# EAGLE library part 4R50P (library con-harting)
CONNECTOR
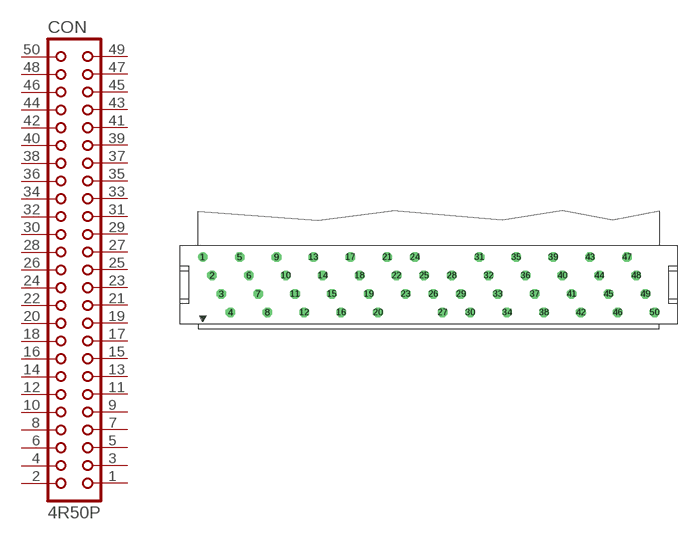
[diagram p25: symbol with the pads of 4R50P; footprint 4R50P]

Designator prefix CON

## 4R50P (OC_FARNELL: unknown; OC_NEWARK: unknown)  [4R50P]
1  1  pas
2  2  pas
3  3  pas
4  4  pas
5  5  pas
6  6  pas
7  7  pas
8  8  pas
9  9  pas
10  10  pas
11  11  pas
12  12  pas
13  13  pas
14  14  pas
15  15  pas
16  16  pas
17  17  pas
18  18  pas
19  19  pas
20  20  pas
21  21  pas
22  22  pas
23  23  pas
24  24  pas
25  25  pas
26  26  pas
27  27  pas
28  28  pas
29  29  pas
30  30  pas
31  31  pas
32  32  pas
33  33  pas
34  34  pas
35  35  pas
36  36  pas
37  37  pas
38  38  pas
39  39  pas
40  40  pas
41  41  pas
42  42  pas
43  43  pas
44  44  pas
45  45  pas
46  46  pas
47  47  pas
48  48  pas
49  49  pas
50  50  pas

## Footprint 4R50P (pad centres in mm)
CONNECTOR
drill 0.813 round: 1 -31.115,3.81
drill 0.813 octagon: 2 -29.845,1.27; 3 -28.575,-1.27; 4 -27.305,-3.81; 5 -26.035,3.81; 6 -24.765,1.27; 7 -23.495,-1.27; 8 -22.225,-3.81; 9 -20.955,3.81; 10 -19.685,1.27; 11 -18.415,-1.27; 12 -17.145,-3.81; 13 -15.875,3.81; 14 -14.605,1.27; 15 -13.335,-1.27; 16 -12.065,-3.81; 17 -10.795,3.81; 18 -9.525,1.27; 19 -8.255,-1.27; 20 -6.985,-3.81; 21 -5.715,3.81; 22 -4.445,1.27; 23 -3.175,-1.27; 24 -1.905,3.81; 25 -0.635,1.27; 26 0.635,-1.27; 27 1.905,-3.81; 28 3.175,1.27; 29 4.445,-1.27; 30 5.715,-3.81; 31 6.985,3.81; 32 8.255,1.27; 33 9.525,-1.27; 34 10.795,-3.81; 35 12.065,3.81; 36 13.335,1.27; 37 14.605,-1.27; 38 15.875,-3.81; 39 17.145,3.81; 40 18.415,1.27; 41 19.685,-1.27; 42 20.955,-3.81; 43 22.225,3.81; 44 23.495,1.27; 45 24.765,-1.27; 46 26.035,-3.81; 47 27.305,3.81; 48 28.575,1.27; 49 29.845,-1.27; 50 31.115,-3.81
